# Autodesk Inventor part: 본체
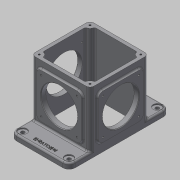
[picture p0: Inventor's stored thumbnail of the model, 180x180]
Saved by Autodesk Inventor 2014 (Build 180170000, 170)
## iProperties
Created: 2018-09
Part Number: 본체
Material: 일반
Document SubType Name: Modeling
Designer: mduedu
Density: 1 g/cm^3
Appearance: 기본값
Author: mduedu
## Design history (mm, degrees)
sketch "스케치1"
  geometry: L1 (90, 52.5)-(-90, 52.5); L2 (-90, 52.5)-(-90, -52.5); L3 (-90, -52.5)-(90, -52.5); L4 (90, -52.5)-(90, 52.5); L5 (90, 52.5)-(-90, -52.5); L6 (-90, 52.5)-(90, -52.5); 1 further point
  constraints: 12 end point, 2 midpoint, 2 parallel, 1 horizontal, 1 perpendicular
  dimensions: "d0" = 180 distance of L3.end L2.end; "d1" = 105 distance of L2.end L1.end
extrude "돌출1" new body sketch "스케치1" distance "d2" = 10; taper "d3" = 0 deg
sketch "스케치2"
  geometry: L1 (-52.5, -52.5)-(52.5, -52.5); L2 (52.5, -52.5)-(52.5, 52.5); L3 (52.5, 52.5)-(-52.5, 52.5); L4 (-52.5, 52.5)-(-52.5, -52.5); L5 (-52.5, -52.5)-(52.5, 52.5); L6 (52.5, -52.5)-(-52.5, 52.5); 1 further point
  constraints: 12 end point, 2 midpoint, 2 parallel, 1 horizontal, 1 perpendicular
  dimensions: "d4" = 105 distance of L3.end L2.end; "d5" = 105 distance of L2.end L1.end
extrude "돌출2" join sketch "스케치2" distance "d6" = 100; taper "d7" = 0 deg
sketch "스케치14"
  geometry: L1 (-52.5, 52.5)-(52.5, 52.5) reference; L2 (52.5, 52.5)-(52.5, -52.5) reference; L3 (52.5, -52.5)-(-52.5, -52.5) reference; L4 (-52.5, -52.5)-(-52.5, 52.5) reference; L5 (46.5, 46.5)-(-46.5, 46.5); L6 (-46.5, 46.5)-(-46.5, -46.5); L7 (-46.5, -46.5)-(46.5, -46.5); L8 (46.5, -46.5)-(46.5, 46.5); 1 further point
  constraints: 8 end point, 3 other
  dimensions: "d85" = 6 distance between parallel lines of L5 L1
extrude "돌출10" cut sketch "스케치14" stored distance "d86" = 10; taper "d87" = 0 deg
fillet "모깎기1" dims "d12" = 7
sketch "스케치15"
  geometry: A1 r 7 centre (-45.5, 45.5) between (-45.5, 52.5) and (-52.5, 45.5) reference; A2 r 7 centre (45.5, 45.5) between (52.5, 45.5) and (45.5, 52.5) reference; A3 r 7 centre (45.5, -45.5) between (45.5, -52.5) and (52.5, -45.5) reference; A4 r 7 centre (-45.5, -45.5) between (-52.5, -45.5) and (-45.5, -52.5) reference; 5 further points
  constraints: 4 coincident, 4 vertical alignment, 8 other
extrude "돌출11" join sketch "스케치15" stored distance "d88" = 10; taper "d89" = 0 deg
fillet "모깎기15" dims "d90" = 3
sketch "스케치6"
  geometry: L1 (50, 17.5)-(130, 17.5); L2 (130, 17.5)-(130, 97.5); L3 (130, 97.5)-(50, 97.5); L4 (50, 97.5)-(50, 17.5); L5 (50, 17.5)-(130, 97.5); L6 (130, 17.5)-(50, 97.5); L7 (0, 0)-(180, 0) reference; 4 further points
  constraints: 12 end point, 4 midpoint, 2 parallel, 1 horizontal, 1 perpendicular, 1 vertical alignment
  dimensions: "d25" = 80 distance of L3.end L2.end; "d26" = 80 distance of L2.end L1.end; "d27" = 57.5 distance of point (90, 0) point (90, 57.5)
extrude "돌출6" join sketch "스케치6" distance "d28" = 3; taper "d29" = 0 deg
fillet "모깎기7" dims "d30" = 8
sketch "스케치7"
  geometry: C1 r 32.5 at (90, 57.5); 1 further point
  constraints: 1 centre point, 1 vertical alignment
  dimensions: "d32" = 65 diameter of C1; "d33" = 57.5 distance of C1.centre point (90, 0)
extrude "돌출7" cut sketch "스케치7" stored distance "d34" = 3; taper "d35" = 0 deg
fillet "모깎기9" dims "d36" = 3
sketch "스케치8"
  geometry: L1 (5.5, 7.5)-(85.5, 7.5); L2 (85.5, 7.5)-(85.5, 87.5); L3 (85.5, 87.5)-(5.5, 87.5); L4 (5.5, 87.5)-(5.5, 7.5); L5 (5.5, 7.5)-(85.5, 87.5); L6 (85.5, 7.5)-(5.5, 87.5); L7 (-7, -10)-(98, -10) reference; C1 r 32.5 at (45.5, 47.5); 4 further points
  constraints: 12 end point, 4 midpoint, 2 parallel, 1 centre point, 1 coincident, 1 horizontal, 1 perpendicular, 1 vertical alignment
  dimensions: "d37" = 80 distance of L3.end L2.end; "d38" = 80 distance of L2.end L1.end; "d39" = 57.5 distance from line of point (45.5, 47.5) L7; "d40" = 65 diameter of C1
extrude "돌출8" join sketch "스케치8" distance "d41" = 3; taper "d42" = 0 deg
fillet "모깎기10" dims "d43" = 8
extrude "돌출9" cut sketch "스케치8" stored distance "d44" = 3; taper "d45" = 0 deg
fillet "모깎기11" dims "d46" = 3
sketch "스케치9"
  geometry: L1 (50, 89.5)-(50, 25.5) reference; L2 (58, 17.5)-(122, 17.5) reference; L3 (130, 25.5)-(130, 89.5) reference; L4 (122, 97.5)-(58, 97.5) reference; C1 r 32.5 at (90, 57.5) reference; A1 r 8 centre (58, 89.5) between (58, 97.5) and (50, 89.5) reference; A2 r 8 centre (58, 25.5) between (50, 25.5) and (58, 17.5) reference; A3 r 8 centre (122, 25.5) between (122, 17.5) and (130, 25.5) reference; A4 r 8 centre (122, 89.5) between (130, 89.5) and (122, 97.5) reference; 5 further points
  constraints: 4 coincident
hole "구멍1" sketch "스케치9" at (58, 89.5), (122, 89.5), (122, 25.5), (58, 25.5) diameter "d47" = 3.242; stored, may be unused: countersink angle "d51" = 90 deg, drill point angle "d53" = 118 deg; dims "d48" = 6, "d49" = 4, "d50" = 2, "d52" = 9
sketch "스케치10" dims "d30" = 8
  geometry: L1 (13.5, 7.5)-(77.5, 7.5) reference; L2 (85.5, 15.5)-(85.5, 79.5) reference; L3 (77.5, 87.5)-(13.5, 87.5) reference; L4 (5.5, 79.5)-(5.5, 15.5) reference; C1 r 32.5 at (45.5, 47.5) reference; A1 r 8 centre (13.5, 15.5) between (5.5, 15.5) and (13.5, 7.5) reference; A2 r 8 centre (77.5, 15.5) between (77.5, 7.5) and (85.5, 15.5) reference; A3 r 8 centre (77.5, 79.5) between (85.5, 79.5) and (77.5, 87.5) reference; A4 r 8 centre (13.5, 79.5) between (13.5, 87.5) and (5.5, 79.5) reference; 5 further points
  constraints: 4 coincident
hole "구멍2" sketch "스케치10" at (13.5, 79.5), (77.5, 79.5), (77.5, 15.5), (13.5, 15.5) diameter "d54" = 3.242; stored, may be unused: countersink angle "d58" = 90 deg, drill point angle "d60" = 118 deg; dims "d30" = 8, "d55" = 6, "d56" = 4, "d57" = 2, "d59" = 9
fillet "모깎기12" dims "d68" = 11
sketch "스케치16"
  geometry: A1 r 11 centre (-79, 41.5) between (-79, 52.5) and (-90, 41.5) reference; A2 r 11 centre (-79, -41.5) between (-90, -41.5) and (-79, -52.5) reference; A3 r 11 centre (79, 41.5) between (90, 41.5) and (79, 52.5) reference; A4 r 11 centre (79, -41.5) between (79, -52.5) and (90, -41.5) reference; 5 further points
  constraints: 4 coincident
hole "구멍5" sketch "스케치16" at (-79, 41.5), (79, 41.5), (79, -41.5), (-79, -41.5) diameter "d91" = 6.6; stored, may be unused: countersink angle "d95" = 90 deg, drill point angle "d97" = 118 deg; dims "d92" = 6, "d93" = 15, "d94" = 2, "d96" = 8
fillet "모깎기13" dims "d77" = 3
fillet "모깎기14" dims "d78" = 3
chamfer "모따기1" distance "d79" = 1; stored, may be unused: second distance "d80" = 2, angle "d81" = 45 deg
sketch "스케치17"
  geometry: A1 r 7 centre (-45.5, 45.5) between (-45.5, 52.5) and (-52.5, 45.5) reference; A2 r 7 centre (-45.5, -45.5) between (-52.5, -45.5) and (-45.5, -52.5) reference; A3 r 7 centre (45.5, -45.5) between (45.5, -52.5) and (52.5, -45.5) reference; A4 r 7 centre (45.5, 45.5) between (52.5, 45.5) and (45.5, 52.5) reference; 5 further points
  constraints: 4 coincident
hole "구멍6" sketch "스케치17" at (-45.5, 45.5), (45.5, 45.5), (45.5, -45.5), (-45.5, -45.5) diameter "d98" = 3.242; stored, may be unused: countersink angle "d102" = 90 deg, drill point angle "d104" = 118 deg; dims "d99" = 8, "d100" = 15, "d101" = 2, "d103" = 10
sketch "스케치13"
  geometry: L1 (90, -41.5)-(90, 41.5) reference; 2 further points
  constraints: 1 horizontal alignment, 1 other
  dimensions: "d82" = 10 distance from line of point (80, 0) L1
feature "엠보싱1" sketch "스케치13" dims "d0" = 180, "d1" = 105, "d25" = 80, "d26" = 80, "d27" = 57.5, "d83" = 0.5, "d84" = 0
node "솔리드1"
mirror "대칭1"
mirror "대칭2"
node "투영된 루프2"
node "투영된 루프3"
node "투영된 루프6"
